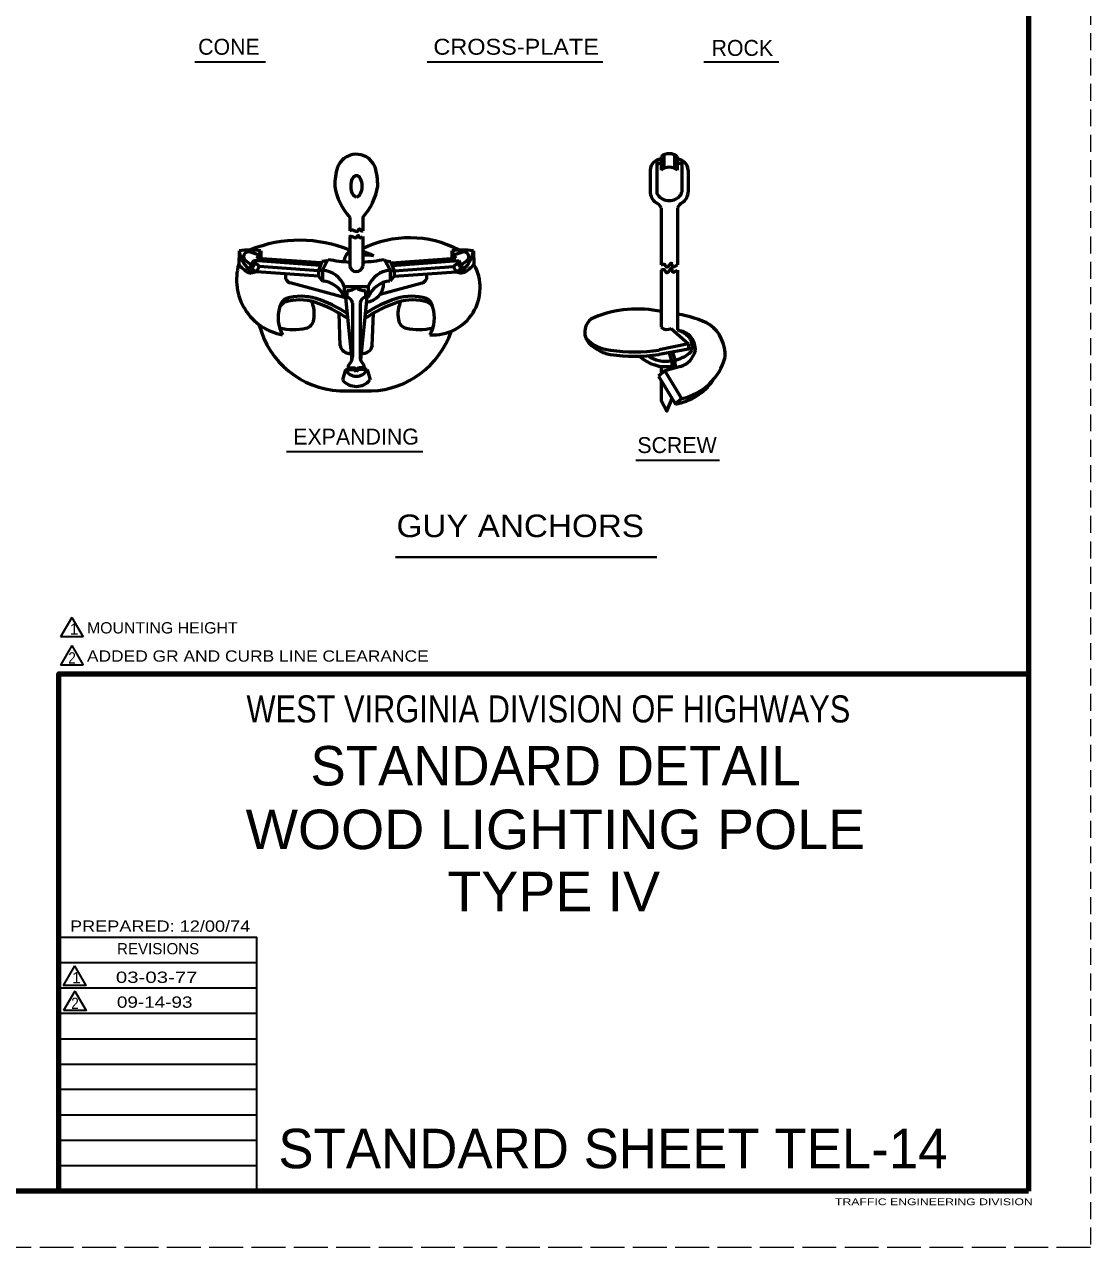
# Model space of a CAD drawing. Extents: x -1 to 679, y 0 to 440.
# Drawn here: x 490.2 to 678.9, y 0.2 to 216.8 of the extents above; entities that cross this region are included whole.
import ezdxf
from ezdxf.enums import TextEntityAlignment as Align

# ---------------------------------------------------------------- set-up
doc = ezdxf.new("R2010")
doc.units = 0
doc.linetypes.add('LONG_DASHED', pattern=[7.5, 6, -1.5])
doc.linetypes.add('MEDIUM_DASHED', pattern=[4.5, 3, -1.5])
doc.layers.add('1', color=7, linetype='Continuous', lineweight=53)
doc.layers.add('61', color=7, linetype='Continuous', lineweight=35)

msp = doc.modelspace()

# ---------------------------------------------------------------- linework, layer by layer
at = {"layer": '1', "linetype": 'MEDIUM_DASHED', "lineweight": 13}
msp.add_line((678.891, 440.242), (678.871, 0.222), dxfattribs=at)
at = {"layer": '1', "lineweight": 35}
for p, q in [((520.296, 210.179), (532.816, 210.179)), ((561.476, 210.179), (592.576, 210.179)), ((610.416, 210.179), (623.696, 210.179)), ((536.524, 141.147), (560.715, 141.147)), ((598.408, 139.646), (613.222, 139.646)), ((498.555, 111.791), (496.555, 108.327)), ((498.555, 111.791), (500.555, 108.327)), ((500.555, 108.327), (496.555, 108.327)), ((498.555, 106.794), (496.555, 103.33)), ((498.555, 106.794), (500.555, 103.33)), ((500.555, 103.33), (496.555, 103.33)), ((531.271, 50.642), (496.291, 50.642)), ((499.03, 50.09), (497.03, 46.626)), ((531.271, 46.142), (496.291, 46.142)), ((499.079, 45.628), (497.079, 42.164)), ((531.271, 41.642), (496.291, 41.642)), ((531.271, 37.122), (496.291, 37.122)), ((531.271, 32.642), (496.291, 32.642)), ((531.271, 28.162), (496.291, 28.162)), ((531.271, 23.662), (496.291, 23.662)), ((531.271, 19.162), (496.291, 19.162)), ((531.271, 14.642), (496.291, 14.642))]:
    msp.add_line(p, q, dxfattribs=at)
at = {"layer": '1'}
for p, q in [((602.855, 193.4), (602.855, 191)), ((603.335, 193.68), (603.335, 191.28)), ((605.255, 193.68), (605.255, 191.28)), ((605.735, 193.4), (605.735, 191)), ((600.935, 191), (600.935, 187.16)), ((602.095, 192.74), (602.095, 187.081)), ((606.515, 192.74), (606.515, 187.06)), ((607.655, 191), (607.655, 187.16)), ((602.895, 184.3), (602.895, 174.22)), ((605.775, 184.3), (605.775, 174.22)), ((547.735, 182.62), (547.735, 180.22)), ((550.075, 182.62), (550.075, 180.22)), ((547.735, 179.261), (547.735, 173.981)), ((550.075, 179.261), (550.075, 173.981)), ((528.175, 176.72), (528.095, 174.32)), ((531.615, 175.96), (530.015, 176.52)), ((532.015, 176.72), (531.275, 175.361)), ((531.615, 175.96), (531.615, 175.34)), ((532.015, 176.72), (532.015, 175.3)), ((565.795, 176.72), (566.535, 175.38)), ((565.795, 176.72), (565.795, 175.32)), ((566.195, 175.96), (567.795, 176.52)), ((566.195, 175.96), (566.195, 175.34)), ((569.635, 176.72), (569.715, 174.32)), ((530.315, 174.201), (529.335, 174.9)), ((530.735, 174.96), (529.915, 173.46)), ((529.915, 173.46), (530.395, 173.481)), ((531.215, 172.981), (530.395, 173.481)), ((542.535, 174.12), (530.735, 174.96)), ((530.995, 174.56), (530.995, 174.94)), ((531.695, 173.9), (530.995, 174.56)), ((531.695, 173.9), (531.215, 172.981)), ((542.695, 174.56), (531.275, 175.361)), ((542.215, 173.16), (531.695, 173.9)), ((543.775, 174.94), (542.835, 174.8)), ((543.895, 175.18), (542.935, 173.261)), ((553.915, 175.18), (554.875, 173.261)), ((554.035, 174.94), (554.975, 174.8)), ((555.115, 174.581), (566.535, 175.38)), ((555.275, 174.12), (567.075, 174.96)), ((555.595, 173.16), (566.115, 173.9)), ((566.115, 173.9), (566.815, 174.56)), ((566.115, 173.9), (566.595, 172.981)), ((566.595, 172.981), (567.415, 173.481)), ((566.815, 174.56), (566.815, 174.94)), ((567.075, 174.96), (567.895, 173.46)), ((567.895, 173.46), (567.415, 173.481)), ((567.495, 174.201), (568.475, 174.9)), ((531.215, 172.981), (530.275, 172.761)), ((542.215, 172.201), (531.215, 172.981)), ((542.935, 173.261), (542.215, 173.16)), ((542.935, 173.261), (542.935, 171.34)), ((554.875, 173.261), (554.875, 171.34)), ((554.875, 173.261), (555.595, 173.16)), ((555.595, 172.201), (566.595, 172.981)), ((566.595, 172.981), (567.535, 172.761)), ((602.895, 173.261), (602.895, 163.18)), ((605.775, 173.261), (605.775, 162.68)), ((546.775, 168.421), (537.215, 171)), ((546.775, 170.38), (551.035, 170.38)), ((546.775, 170.38), (546.775, 168.421)), ((547.255, 169.66), (547.255, 168.46)), ((550.555, 169.66), (550.555, 168.46)), ((551.035, 170.38), (551.035, 168.46)), ((553.155, 169), (560.575, 171)), ((546.775, 168.46), (547.255, 168.46)), ((547.015, 168.46), (548.135, 157.361)), ((548.215, 167.5), (548.215, 157.9)), ((549.595, 167.5), (549.595, 157.9)), ((550.795, 168.46), (549.675, 157.361)), ((550.555, 168.46), (551.035, 168.46)), ((546.075, 159.9), (545.875, 165.66)), ((551.735, 159.9), (551.935, 165.66)), ((604.675, 162.96), (607.715, 160.24)), ((607.715, 160.24), (602.535, 159.141)), ((604.875, 158.78), (605.295, 157.4)), ((547.455, 156), (548.415, 156)), ((550.335, 156), (549.375, 156)), ((602.895, 156.24), (602.895, 154.9)), ((606.295, 156.201), (603.515, 155.46)), ((605.295, 157.4), (605.375, 155.96)), ((546.995, 155.68), (546.495, 153.84)), ((546.995, 155.68), (548.435, 155.68)), ((550.835, 155.68), (549.395, 155.68)), ((550.835, 155.68), (551.335, 153.84)), ((603.515, 155.46), (602.435, 154.5)), ((602.435, 154.5), (605.415, 149.56)), ((603.515, 155.46), (606.475, 150.52)), ((545.975, 151.9), (551.595, 151.9)), ((606.475, 150.52), (605.415, 149.56))]:
    msp.add_line(p, q, dxfattribs=at)
at = {"layer": '1', "lineweight": 13}
msp.add_line((602.895, 154.96), (602.895, 154.78), dxfattribs=at)
at = {"layer": '1', "lineweight": 40}
msp.add_line((555.839, 122.434), (602.094, 122.434), dxfattribs=at)
at = {"layer": '1'}
for points in [[(529.915, 173.46), (529.795, 172.84), (530.275, 172.761)], [(530.995, 174.56), (530.395, 173.481), (530.275, 172.761)], [(542.835, 174.8), (542.215, 173.16), (542.215, 172.201), (542.935, 171.34)], [(554.975, 174.8), (555.595, 173.16), (555.595, 172.201), (554.875, 171.34)], [(566.815, 174.56), (567.415, 173.481), (567.535, 172.761)], [(567.895, 173.46), (568.015, 172.84), (567.535, 172.761)], [(607.715, 160.24), (607.715, 159.28), (602.515, 158.361)], [(604.315, 158.6), (604.735, 157.22), (604.815, 155.78)], [(602.895, 153.74), (602.895, 150.22), (603.855, 148.3), (604.815, 150.541)]]:
    msp.add_lwpolyline(points, dxfattribs=at)
at = {"layer": '1', "lineweight": 158}
msp.add_lwpolyline([(496.271, 10.202), (496.271, 101.782), (667.931, 101.782)], dxfattribs=at)
at = {"layer": '1', "lineweight": 35}
for points in [[(531.271, 10.162), (531.271, 55.122), (496.291, 55.122)], [(499.03, 50.09), (501.03, 46.626), (497.03, 46.626)], [(499.079, 45.628), (501.079, 42.164), (497.079, 42.164)]]:
    msp.add_lwpolyline(points, dxfattribs=at)
at = {"layer": '1'}
for centre, radius, start, end in [((549.784, 189.61), 4.605, 131.96494, 155.64508), ((548.794, 190.204), 3.517, 114.18463, 126.44768), ((548.932, 190.285), 3.504, 51.67793, 116.77606), ((548.026, 189.61), 4.605, 24.35492, 48.03506), ((602.948, 190.916), 2.008, 92.45547, 177.54453), ((604.302, 191.539), 2.355, 52.29201, 127.70799), ((605.656, 190.916), 2.008, 2.45547, 87.54453), ((556.397, 188.212), 11.3, 163.03649, 180.34718), ((541.413, 188.212), 11.3, 359.65283, 16.96351), ((602.83, 191.134), 1.069, 88.28293, 133.52461), ((604.302, 189.139), 2.355, 52.29201, 127.70799), ((605.774, 191.134), 1.069, 46.47539, 91.71707), ((556.163, 190.044), 11.228, 189.74744, 221.3725), ((541.647, 190.044), 11.228, 318.6275, 350.25256), ((603.304, 187.18), 2.363, 180.43177, 234.62969), ((602.81, 187.062), 0.716, 179.14798, 220.24311), ((604.302, 188.131), 2.55, 216.91814, 322.98043), ((605.791, 187.059), 0.716, 319.75689, 0.85202), ((605.299, 187.18), 2.363, 305.37031, 359.56823), ((601.102, 183.459), 1.979, 24.94304, 65.05696), ((607.512, 183.577), 1.878, 116.76572, 157.56298), ((538.872, 155.573), 22.999, 67.32753, 112.30219), ((558.324, 160.355), 18.65, 62.24214, 116.49544), ((530.098, 158.421), 18.391, 84.00757, 95.99243), ((532.887, 177.138), 4.728, 185.18056, 230.94579), ((529.846, 175.636), 0.896, 78.96142, 235.46809), ((549.383, 174.552), 2.645, 128.46984, 175.06692), ((546.761, 164.717), 12.274, 64.65247, 74.23543), ((550.472, 166.595), 9.343, 80.48984, 92.29918), ((567.712, 158.421), 18.391, 84.00757, 95.99243), ((567.936, 175.624), 0.903, 306.45493, 99.11556), ((564.923, 177.138), 4.728, 309.05421, 354.81944), ((537.63, 171.581), 9.92, 164.01359, 259.79898), ((532.649, 177.857), 5.771, 217.89069, 240.44911), ((542.621, 168.842), 4.433, 20.35078, 85.90942), ((549.965, 208.12), 33.491, 259.56289, 266.18708), ((548.905, 174.219), 1.191, 191.39485, 348.60515), ((547.845, 208.12), 33.491, 273.81292, 280.43711), ((555.188, 168.842), 4.433, 94.09058, 159.64922), ((562.494, 170.14), 8.34, 266.16365, 30.02378), ((565.161, 177.857), 5.771, 299.55089, 322.10931), ((537.604, 172.162), 1.235, 158.99371, 251.37679), ((542.621, 166.922), 4.433, 20.35078, 85.90942), ((555.188, 166.922), 4.433, 94.09058, 159.64922), ((560.178, 172.162), 1.235, 288.62321, 21.00629), ((547.469, 171.591), 1.94, 263.73433, 317.75599), ((550.341, 171.591), 1.94, 222.24401, 276.26567), ((550.442, 170.915), 3.301, 273.98395, 2.60406), ((537.356, 166.426), 2.029, 115.12547, 173.42944), ((537.18, 165.727), 2.062, 116.11742, 153.15373), ((538.913, 159.366), 8.626, 72.17801, 107.82199), ((539.135, 159.22), 9.42, 73.72458, 106.27542), ((536.47, 165.516), 5.008, 348.82631, 26.25382), ((534.557, 146.028), 22.657, 55.49077, 72.01683), ((534.557, 146.028), 23.377, 56.96697, 72.01675), ((547.13, 167.376), 1.094, 6.66371, 83.33629), ((550.679, 167.376), 1.094, 96.66371, 173.33629), ((563.252, 146.028), 22.657, 107.98317, 124.50923), ((563.252, 146.028), 23.377, 107.98325, 123.03303), ((558.675, 159.22), 9.42, 73.72458, 106.27542), ((558.897, 159.366), 8.626, 72.17801, 107.82199), ((561.288, 165.516), 5.008, 153.74618, 191.17369), ((560.453, 166.426), 2.029, 6.57056, 64.87453), ((560.63, 165.727), 2.062, 26.84627, 63.88258), ((541.045, 164.837), 5.987, 162.29086, 210.27517), ((556.765, 164.837), 5.987, 329.72483, 17.70914), ((592.128, 162.321), 2.779, 112.56326, 201.22601), ((598.632, 146.644), 19.752, 77.48956, 112.53539), ((602.483, 145.675), 20.095, 63.12438, 80.5666), ((546.789, 167.427), 15.548, 194.44102, 266.97322), ((537.81, 173.121), 10.356, 256.06592, 282.21618), ((539.63, 164.722), 1.762, 282.14771, 354.26068), ((550.97, 167.427), 15.548, 272.30306, 341.28411), ((558.128, 164.722), 1.762, 185.73932, 257.85229), ((559.948, 173.121), 10.356, 257.78382, 283.93408), ((603.935, 164.324), 1.55, 227.92906, 298.55891), ((603.808, 157.173), 5.853, 47.97836, 70.34854), ((606.003, 160.031), 2.497, 60.03867, 86.11071), ((607.459, 158.218), 6.756, 357.06801, 53.01462), ((638.71, 184.313), 54.284, 205.06602, 205.618), ((594.274, 165.44), 6.316, 221.76894, 266.63849), ((592.227, 162.217), 2.818, 205.89722, 222.96556), ((594.928, 165.152), 6.802, 225.54603, 243.17205), ((605.377, 159.135), 3.586, 37.20204, 58.52155), ((605.846, 159.779), 2.563, 345.49101, 42.81927), ((605.345, 159.167), 3.593, 358.21611, 36.4931), ((547.706, 160.202), 1.659, 186.64556, 280.42286), ((550.104, 160.202), 1.659, 259.57714, 353.35444), ((594.724, 163.871), 5.581, 239.10628, 261.18034), ((598.188, 186.223), 28.2, 261.18821, 278.81179), ((598.224, 187.002), 28.2, 261.18821, 278.81179), ((603.74, 162.949), 5.809, 235.85618, 279.93742), ((603.724, 164.026), 6.875, 282.93456, 306.7285), ((605.093, 159.969), 3.95, 287.7219, 346.62294), ((606.558, 160.035), 1.984, 310.05064, 333.08561), ((548.667, 155.997), 1.202, 126.91323, 179.95667), ((546.183, 157.978), 2.036, 329.93461, 357.90459), ((548.316, 155.409), 0.599, 10.44919, 79.5508), ((549.493, 155.409), 0.599, 100.4492, 169.55081), ((551.627, 157.978), 2.036, 182.09541, 210.06539), ((549.143, 155.997), 1.202, 0.04333, 53.08677), ((603.74, 162.949), 6.769, 226.52134, 278.94966), ((604.422, 160.424), 10.112, 281.74498, 345.38421), ((548.911, 155.799), 3.115, 219.10281, 320.89719), ((548.911, 156.626), 2.136, 205.98923, 334.01077), ((548.322, 155.101), 0.599, 10.44919, 79.5508), ((549.499, 155.101), 0.599, 100.4492, 169.55081), ((603.707, 159.578), 10.162, 279.6497, 325.48694)]:
    msp.add_arc(centre, radius, start, end, dxfattribs=at)
msp.add_ellipse((548.937, 188.143), major_axis=(0, -1.92), ratio=0.5, dxfattribs=at)
for points in [[(547.735, 180.22), (548.095, 180.421), (548.495, 180.3), (549.155, 180.201), (549.475, 180.581), (549.855, 180.22), (550.075, 180.22)], [(547.735, 179.261), (547.935, 179.32), (548.875, 179.06), (549.275, 179.421), (549.495, 179.06), (550.075, 179.261)], [(602.895, 174.22), (603.415, 174.32), (603.895, 173.78), (604.675, 174.54), (604.835, 174), (605.775, 174.22)], [(602.895, 173.261), (603.415, 173.361), (603.895, 172.82), (604.675, 173.581), (604.835, 173.04), (605.775, 173.261)]]:
    msp.add_spline(points, degree=3, dxfattribs=at)
at = {"layer": '61', "lineweight": 158}
for p, q in [((667.911, 430.242), (667.931, 10.202)), ((667.931, 10.202), (28.871, 10.222))]:
    msp.add_line(p, q, dxfattribs=at)
at = {"layer": '61', "linetype": 'LONG_DASHED', "lineweight": 13}
msp.add_line((678.871, 0.222), (-1.189, 0.202), dxfattribs=at)

# ---------------------------------------------------------------- texts
at = {"layer": '1'}
for s, height, p in [('CONE', 2.822, (526.359, 211.419)), ('ROCK', 2.822, (617.245, 211.219)), ('EXPANDING', 2.822, (548.866, 142.387)), ('SCREW', 2.822, (605.687, 140.886)), ('STANDARD DETAIL', 6.993, (584.188, 82.022))]:
    msp.add_text(s, height=height, dxfattribs=at).set_placement(p, align=Align.CENTER)
for s, height, width, p in [('CROSS-PLATE', 2.822, 1.1, (577.207, 211.419)), ('WEST VIRGINIA DIVISION OF HIGHWAYS', 4.795, 0.85, (582.919, 93.182)), ('WOOD LIGHTING POLE', 6.993, 1.05, (584.141, 70.754)), ('TYPE IV', 6.993, 1.05, (583.866, 59.762)), ('03-03-77', 2, 1.35, (513.571, 47.062)), ('09-14-93', 2, 1.25, (513.22, 42.662))]:
    msp.add_text(s, height=height, dxfattribs=dict(at, width=width)).set_placement(p, align=Align.CENTER)
for s, height, width, p in [('GUY ANCHORS', 4, 1.1, (556.027, 125.998)), ('MOUNTING HEIGHT', 2, 1.05, (501.225, 108.94)), ('2', 2, 0.9, (497.918, 103.611)), ('ADDED GR AND CURB LINE CLEARANCE', 2, 1.15, (501.225, 103.943)), ('PREPARED: 12/00/74', 1.998, 1.2, (498.231, 56.122)), ('2', 2, 0.9, (498.442, 42.445)), ('TRAFFIC ENGINEERING DIVISION', 1.2, 1.35, (633.651, 7.702))]:
    msp.add_text(s, height=height, dxfattribs=dict(at, width=width)).set_placement(p)
for s, height, p in [('1', 2, (498.221, 108.735)), ('REVISIONS', 1.998, (506.551, 52.122)), ('1', 2, (498.64, 46.995)), ('STANDARD SHEET TEL-14', 6.993, (535.111, 14.242))]:
    msp.add_text(s, height=height, dxfattribs=at).set_placement(p)

doc.saveas('drawing.dxf')
